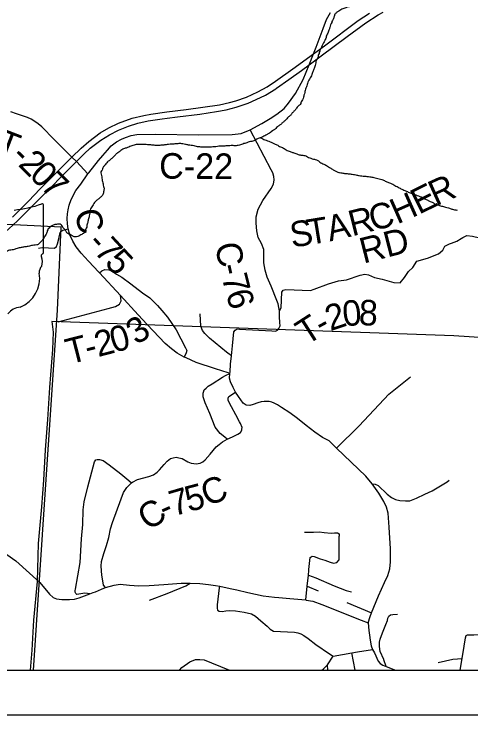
# Model space of a CAD drawing. Extents: x -20.2 to 34, y 0 to 22.
# Drawn here: x 3.418 to 4.435, y 14 to 15.559 of the extents above; entities that cross this region are included whole.
import ezdxf

# ---------------------------------------------------------------- set-up
doc = ezdxf.new("R2010")
doc.units = 0
for name, color, linetype in [('Default', 7, 'Continuous'), ('GM_X_City_Street', 7, 'Continuous'), ('GM_X_County_Road', 7, 'Continuous'), ('GM_X_County_Road_Text', 7, 'Continuous'), ('GM_X_Minor_River', 7, 'Continuous'), ('GM_X_State_Route', 7, 'Continuous'), ('GM_X_State_Shield', 7, 'Continuous'), ('GM_X_Township_Road', 7, 'Continuous'), ('GM_X_Township_Road_Text', 7, 'Continuous'), ('SH_Cut_Line', 7, 'Continuous'), ('SH_Data', 7, 'Continuous')]:
    doc.layers.add(name, color=color, linetype=linetype)

msp = doc.modelspace()

# ---------------------------------------------------------------- linework, layer by layer
at = {"layer": 'Default'}
for points in [[(4.5, 19.1063), (4.129, 19.1285), (4.084, 19.1299), (2.9253, 19.1951), (2.1, 19.2514), (2.1, 14.1), (5.3953, 14.1)], [(4.4653, 14.8388), (4.3965, 14.843), (3.5022, 14.8753), (3.505, 14.8511), (3.5035, 14.8128), (3.4972, 14.7282), (3.4927, 14.6569), (3.487, 14.5895), (3.4833, 14.522), (3.4792, 14.4632), (3.4719, 14.3817), (3.4691, 14.2968), (3.461, 14.2107), (3.4573, 14.144), (3.454, 14.1), (5.4224, 14.1)]]:
    msp.add_lwpolyline(points, dxfattribs=at)
msp.add_lwpolyline([(3.3273, 14.1), (3.4615, 14.1), (3.4877, 14.5012), (3.5149, 14.9006), (3.5228, 15.0852), (2.4641, 15.1369), (2.4117, 14.1451)], close=True, dxfattribs=at)
at = {"layer": 'GM_X_City_Street'}
for p, q in [((4.0705, 14.2863), (4.095, 14.2764)), ((4.1583, 14.2505), (4.2138, 14.2271)), ((4.1771, 14.1), (4.17, 14.1383)), ((4.116, 14.1), (4.1153, 14.1119))]:
    msp.add_line(p, q, dxfattribs=at)
for points in [[(3.6082, 14.9837), (3.6134, 14.9879), (3.6203, 14.9908), (3.6287, 14.9904), (3.6352, 14.9877), (3.6461, 14.9801), (3.6581, 14.9734), (3.6776, 14.9593), (3.704, 14.9392), (3.72, 14.9275), (3.737, 14.9111), (3.747, 14.8998), (3.7594, 14.8851), (3.7695, 14.8704), (3.7791, 14.8565), (3.7999, 14.8169), (3.8022, 14.8104), (3.8014, 14.8054), (3.7968, 14.7961)], [(3.9016, 14.7987), (3.8908, 14.8073), (3.8527, 14.8384), (3.8423, 14.8488), (3.8371, 14.8553), (3.834, 14.8646), (3.8319, 14.8921)], [(3.8984, 14.7595), (3.8987, 14.7631), (3.8998, 14.78), (3.9016, 14.7987), (3.9039, 14.8211), (3.907, 14.8522), (3.9099, 14.856), (3.9147, 14.8585), (3.9201, 14.858), (3.9918, 14.8542), (3.9997, 14.8537), (4.0042, 14.8558), (4.0076, 14.8596), (4.01, 14.8657)], [(4.1356, 14.5931), (4.186, 14.6429), (4.2524, 14.7135), (4.3005, 14.7522)], [(3.5869, 14.2692), (3.5816, 14.2704), (3.5754, 14.2708), (3.5578, 14.2683), (3.5552, 14.2704), (3.554, 14.2728), (3.5539, 14.277), (3.5549, 14.2802), (3.5652, 14.3393), (3.5684, 14.3918), (3.5709, 14.4234), (3.5721, 14.4566), (3.5739, 14.4743), (3.5823, 14.5071), (3.5969, 14.5633), (3.6001, 14.5678), (3.603, 14.5684), (3.6078, 14.5682), (3.616, 14.5659), (3.6298, 14.5566), (3.6558, 14.5362), (3.6738, 14.5218), (3.6794, 14.5161)], [(4.2153, 14.5138), (4.222, 14.5136), (4.2281, 14.5102), (4.2486, 14.4909), (4.258, 14.4838), (4.2673, 14.4796), (4.2767, 14.4773), (4.2889, 14.4764), (4.299, 14.476), (4.3135, 14.4819), (4.3319, 14.4909), (4.3487, 14.4989), (4.3818, 14.5188), (4.3867, 14.5219)], [(4.0644, 14.4064), (4.0848, 14.4068), (4.0974, 14.4072), (4.1083, 14.4057), (4.1236, 14.4043), (4.1312, 14.4054), (4.1381, 14.4049), (4.1418, 14.4028), (4.1416, 14.398)], [(4.0772, 14.3499), (4.0814, 14.3533), (4.0857, 14.3523), (4.0995, 14.3474), (4.11, 14.3443), (4.1217, 14.3396), (4.1293, 14.3375), (4.1364, 14.3388), (4.1418, 14.3454), (4.1416, 14.398)], [(4.0738, 14.3215), (4.0739, 14.3233), (4.0772, 14.3499)], [(4.0673, 14.2558), (4.0705, 14.2863), (4.073, 14.3107), (4.0738, 14.3215)], [(4.073, 14.3107), (4.0898, 14.3052), (4.1307, 14.2874), (4.1572, 14.2765), (4.1687, 14.2742)], [(3.7197, 14.2554), (3.7589, 14.2701), (3.8006, 14.2874), (3.8096, 14.2933)], [(3.8759, 14.2865), (3.8743, 14.2827), (3.8703, 14.2453), (3.8703, 14.2374), (3.8707, 14.2329), (3.8745, 14.2306), (3.8815, 14.2302), (3.889, 14.232), (3.8973, 14.2327), (3.9106, 14.2318), (3.9302, 14.2286), (3.9465, 14.2248), (3.9557, 14.22), (3.9672, 14.2094), (3.9812, 14.1977), (3.9879, 14.1912), (3.9958, 14.1862), (4.0109, 14.1858), (4.0263, 14.1853), (4.0425, 14.1842), (4.0499, 14.1828), (4.0562, 14.1806), (4.063, 14.177), (4.0727, 14.17), (4.0894, 14.1571), (4.1198, 14.1362), (4.1284, 14.131)], [(4.411, 14.1), (4.4154, 14.1253), (4.4198, 14.1531), (4.4225, 14.1718), (4.4242, 14.1766), (4.4272, 14.1781), (4.4311, 14.1781), (4.4414, 14.1783), (4.453, 14.1789), (4.4897, 14.1813), (4.4976, 14.1829), (4.5025, 14.1854), (4.5062, 14.1915), (4.5092, 14.2008), (4.5142, 14.2102), (4.5199, 14.2163), (4.5461, 14.2289), (4.5662, 14.2392)], [(4.2407, 14.1231), (4.2331, 14.1409), (4.2312, 14.1521), (4.2312, 14.162), (4.2327, 14.1687), (4.2382, 14.1827), (4.2457, 14.2016), (4.249, 14.2102), (4.2501, 14.2152), (4.2522, 14.2199), (4.2558, 14.2228), (4.261, 14.2236), (4.2713, 14.2245)], [(4.1284, 14.131), (4.17, 14.1383), (4.1822, 14.1401), (4.2156, 14.1454)], [(4.1033, 14.1), (4.1065, 14.1023), (4.1153, 14.1119), (4.1284, 14.131)], [(4.3619, 14.1168), (4.3942, 14.124), (4.4154, 14.1253)], [(3.7863, 14.1), (3.7914, 14.1053), (3.8091, 14.1183), (3.8217, 14.1235), (3.8317, 14.1237), (3.8413, 14.1225), (3.8941, 14.1013), (3.898, 14.1)], [(4.2461, 14.108), (4.2411, 14.1223), (4.2407, 14.1231)]]:
    msp.add_lwpolyline(points, dxfattribs=at)
at = {"layer": 'GM_X_County_Road'}
for p, q in [((3.8961, 14.7086), (3.9111, 14.7178)), ((3.9196, 14.6521), (3.9113, 14.6679))]:
    msp.add_line(p, q, dxfattribs=at)
for points in [[(3.6156, 15.2444), (3.6256, 15.2566), (3.6342, 15.2662), (3.6461, 15.2748), (3.6568, 15.2807), (3.6662, 15.2847), (3.6784, 15.2885), (3.6916, 15.291), (3.7332, 15.2916), (3.8274, 15.2907), (3.9037, 15.2908), (3.9232, 15.2931), (3.9435, 15.3017), (3.9697, 15.3154), (3.9879, 15.3265), (4.003, 15.3361), (4.0188, 15.3486), (4.0287, 15.361), (4.0445, 15.3824), (4.0616, 15.4135), (4.0745, 15.446), (4.0842, 15.4703), (4.0905, 15.485), (4.1061, 15.5269), (4.1137, 15.547), (4.1223, 15.5627)], [(4.0085, 14.897), (4.0085, 14.8986), (4.0076, 14.906), (4.006, 14.9148), (4.0026, 14.9216), (3.9906, 14.9534), (3.9812, 14.9739), (3.9767, 14.9895), (3.9742, 15.0059), (3.9737, 15.0354), (3.9688, 15.0487), (3.9613, 15.0623), (3.9582, 15.0767), (3.9568, 15.0938), (3.9571, 15.108), (3.9613, 15.1249), (3.9719, 15.1443), (3.9904, 15.1709), (3.9958, 15.1809), (3.997, 15.1899), (3.9963, 15.1973), (3.9938, 15.2059), (3.9902, 15.2126), (3.9435, 15.3017)], [(3.5841, 15.2061), (3.6062, 15.2329), (3.6156, 15.2444)], [(3.5557, 15.1662), (3.5664, 15.1809), (3.5822, 15.2038), (3.5841, 15.2061)], [(3.5387, 15.0813), (3.5369, 15.0926), (3.536, 15.1045), (3.5371, 15.115), (3.5383, 15.1232), (3.5406, 15.1339), (3.545, 15.1465), (3.5557, 15.1662)], [(3.5185, 15.0626), (3.5205, 15.0728), (3.5243, 15.0766), (3.5269, 15.0783), (3.5387, 15.0813)], [(3.6082, 14.9837), (3.6067, 14.9852), (3.5834, 15.0097), (3.5677, 15.0269), (3.5561, 15.0414), (3.5488, 15.0535), (3.5419, 15.068), (3.5387, 15.0813)], [(3.4727, 15.038), (3.4802, 15.0401), (3.4947, 15.0391), (3.5081, 15.0386), (3.5127, 15.0418), (3.5146, 15.0481), (3.5184, 15.0619), (3.5185, 15.0626)], [(3.7968, 14.7961), (3.7808, 14.8051), (3.7682, 14.8144), (3.7542, 14.8263), (3.741, 14.84), (3.7145, 14.8685), (3.6944, 14.8903), (3.6549, 14.9329), (3.6082, 14.9837)], [(4.01, 14.8657), (4.0094, 14.8729), (4.0085, 14.8853), (4.0085, 14.897)], [(3.8945, 14.7608), (3.8662, 14.7699), (3.8231, 14.7841), (3.8008, 14.7942), (3.7968, 14.7961)], [(3.8462, 14.7275), (3.8498, 14.7311), (3.8592, 14.7367), (3.8819, 14.7513), (3.8883, 14.7548), (3.8984, 14.7595)], [(3.9807, 14.6975), (3.9746, 14.6975), (3.9683, 14.6964), (3.9604, 14.6941), (3.9505, 14.6903), (3.9424, 14.6887), (3.9347, 14.6889), (3.9282, 14.6932), (3.9178, 14.7082), (3.9111, 14.7178), (3.9059, 14.7282), (3.9, 14.741), (3.8975, 14.7489), (3.8984, 14.7595), (3.8945, 14.7608)], [(3.8924, 14.6133), (3.8874, 14.6182), (3.8767, 14.6262), (3.8655, 14.6398), (3.8536, 14.6709), (3.843, 14.6944), (3.8387, 14.7074), (3.8387, 14.7155), (3.8396, 14.7183), (3.8414, 14.7232), (3.8455, 14.7268), (3.8462, 14.7275)], [(3.9113, 14.6679), (3.9023, 14.6853), (3.8946, 14.6991), (3.8946, 14.7047), (3.8961, 14.7086)], [(4.2058, 14.2047), (4.2106, 14.2191), (4.2138, 14.2271), (4.2289, 14.2652), (4.2423, 14.2943), (4.2499, 14.3101), (4.2541, 14.3252), (4.2562, 14.3404), (4.256, 14.3696), (4.253, 14.4175), (4.2507, 14.4491), (4.2467, 14.4624), (4.2413, 14.4747), (4.2302, 14.4932), (4.2153, 14.5138), (4.201, 14.5308), (4.1356, 14.5931), (4.119, 14.6094), (4.1045, 14.6174), (4.0871, 14.6291), (4.0684, 14.6436), (4.0486, 14.6592), (4.0315, 14.6718), (4.0132, 14.684), (4.0044, 14.6896), (3.9972, 14.6935), (3.9915, 14.6955), (3.9857, 14.6971), (3.9807, 14.6975)], [(3.9249, 14.6355), (3.9255, 14.6391), (3.9217, 14.6481), (3.9196, 14.6521)], [(3.8973, 14.6157), (3.9054, 14.6195), (3.916, 14.6245), (3.9221, 14.6283), (3.9246, 14.6337), (3.9249, 14.6355)], [(3.6214, 14.2838), (3.6171, 14.2886), (3.616, 14.2938), (3.6137, 14.3113), (3.6121, 14.3309), (3.6128, 14.3415), (3.618, 14.3594), (3.6241, 14.3767), (3.6286, 14.3945), (3.6326, 14.4141), (3.6372, 14.4281), (3.6565, 14.4809), (3.6615, 14.4948), (3.6687, 14.5059), (3.6746, 14.5122), (3.6794, 14.5161), (3.6818, 14.5181), (3.6928, 14.5237), (3.7176, 14.5302), (3.7282, 14.5343), (3.7364, 14.5397), (3.742, 14.5456), (3.7521, 14.5571), (3.7589, 14.5647), (3.7663, 14.5701), (3.7724, 14.5719), (3.779, 14.5731), (3.7848, 14.5722), (3.7918, 14.5701), (3.8049, 14.5634), (3.8119, 14.5602), (3.818, 14.5591), (3.8236, 14.5586), (3.8322, 14.5604), (3.8384, 14.5633), (3.8437, 14.5674), (3.8543, 14.5801), (3.868, 14.5965), (3.8748, 14.6019), (3.882, 14.6073), (3.8924, 14.6133), (3.8973, 14.6157)], [(3.2968, 14.3829), (3.3253, 14.3816), (3.38, 14.3661), (3.402, 14.3566), (3.4223, 14.3426), (3.4757, 14.2947), (3.4967, 14.2687), (3.5048, 14.2611), (3.5127, 14.2584), (3.5246, 14.2571)], [(3.5246, 14.2571), (3.5256, 14.257), (3.5414, 14.2566), (3.5524, 14.2577), (3.5632, 14.2606), (3.5869, 14.2692), (3.5937, 14.2721), (3.5991, 14.2741), (3.6124, 14.2798), (3.6214, 14.2838), (3.6408, 14.289), (3.6538, 14.2906), (3.6746, 14.2886), (3.6956, 14.2874), (3.7188, 14.2883), (3.751, 14.2904), (3.7902, 14.2929), (3.8096, 14.2933), (3.8315, 14.2922), (3.8509, 14.2899), (3.866, 14.2879), (3.8759, 14.2865), (3.8993, 14.2815)], [(3.8993, 14.2815), (3.914, 14.2784), (3.9383, 14.2726), (3.9728, 14.2651), (3.9976, 14.2624)], [(3.9976, 14.2624), (4.0076, 14.2613), (4.0319, 14.259), (4.0673, 14.2558), (4.0684, 14.2557), (4.0831, 14.2534), (4.1027, 14.246), (4.1904, 14.2108), (4.2058, 14.2047), (4.2077, 14.188), (4.2101, 14.1721)], [(4.2101, 14.1721), (4.2102, 14.1711), (4.2129, 14.154), (4.2156, 14.1454), (4.22, 14.1382), (4.2287, 14.1199), (4.2327, 14.1143), (4.2388, 14.1108), (4.2461, 14.108), (4.2668, 14.1)]]:
    msp.add_lwpolyline(points, dxfattribs=at)
at = {"layer": 'GM_X_Minor_River'}
for points in [[(4.262, 15.6083), (4.2521, 15.6061), (4.2479, 15.6046), (4.2434, 15.6035), (4.2285, 15.599), (4.224, 15.5972), (4.2198, 15.5961), (4.2099, 15.5924), (4.2027, 15.589), (4.1985, 15.5875), (4.1943, 15.5856), (4.1897, 15.5838), (4.1844, 15.5815), (4.1783, 15.5789), (4.1737, 15.5778), (4.168, 15.5767), (4.1635, 15.5753), (4.1593, 15.5741), (4.154, 15.5719), (4.1498, 15.5704), (4.1456, 15.5686), (4.1406, 15.5656), (4.1353, 15.5618), (4.1315, 15.5573), (4.1295, 15.5501), (4.1264, 15.5448), (4.1249, 15.5402), (4.1226, 15.5353), (4.121, 15.5293), (4.1183, 15.5232), (4.1168, 15.5187), (4.1152, 15.5145), (4.1129, 15.5096), (4.1117, 15.5047), (4.1094, 15.4998), (4.1067, 15.4948), (4.1036, 15.4888), (4.1009, 15.4824), (4.0982, 15.4767), (4.0967, 15.4714), (4.0951, 15.4665), (4.0939, 15.4619), (4.0909, 15.457), (4.0893, 15.4502), (4.0885, 15.4449), (4.0869, 15.4403), (4.0854, 15.4362), (4.0823, 15.429), (4.0808, 15.4244), (4.0784, 15.4195), (4.0757, 15.4142), (4.0731, 15.4101), (4.0711, 15.4048), (4.0696, 15.3995), (4.0676, 15.3942), (4.0657, 15.3892), (4.0653, 15.3847), (4.0633, 15.3786), (4.0622, 15.3741), (4.0602, 15.368), (4.0568, 15.3639), (4.056, 15.3597), (4.0502, 15.3541), (4.0468, 15.3499), (4.0422, 15.3439), (4.0372, 15.339), (4.0338, 15.3341), (4.0288, 15.3303), (4.025, 15.3262), (4.0208, 15.3216), (4.0154, 15.3171), (4.0105, 15.3126), (4.0044, 15.3085), (4.0005, 15.3043), (3.9952, 15.3006), (3.9906, 15.2972), (3.9864, 15.2942), (3.9811, 15.2912), (3.9761, 15.2882), (3.9678, 15.2845), (3.9636, 15.283), (3.9586, 15.2807), (3.9537, 15.2781), (3.9495, 15.2766), (3.9445, 15.2752), (3.9388, 15.2737), (3.9339, 15.2718), (3.9297, 15.2707), (3.9194, 15.2674), (3.9103, 15.2659), (3.9058, 15.2663), (3.9012, 15.2664), (3.8959, 15.266), (3.8917, 15.2657), (3.8872, 15.2654), (3.883, 15.265), (3.8784, 15.2654)], [(3.9664, 15.284), (3.9764, 15.2791), (3.9821, 15.2771), (3.9878, 15.2748), (3.992, 15.2736), (3.9976, 15.2702), (4.0048, 15.2671), (4.009, 15.2644), (4.0131, 15.2629), (4.0214, 15.2582), (4.0256, 15.2555), (4.0301, 15.254), (4.0343, 15.2524), (4.0407, 15.2505), (4.0453, 15.2489), (4.0525, 15.2462), (4.0566, 15.2454), (4.0608, 15.245), (4.0691, 15.2427), (4.0737, 15.24), (4.0786, 15.2381), (4.0843, 15.2365), (4.0884, 15.2353), (4.0941, 15.2334), (4.1005, 15.2284), (4.1054, 15.2261), (4.1137, 15.2218), (4.1179, 15.2191), (4.1228, 15.2161), (4.13, 15.2118), (4.1353, 15.2091), (4.1425, 15.2064), (4.1478, 15.2056), (4.1519, 15.2048), (4.1595, 15.204), (4.1682, 15.2032), (4.1732, 15.2024), (4.1789, 15.2012), (4.1861, 15.1996), (4.1917, 15.1988), (4.1989, 15.1984), (4.2035, 15.198), (4.2099, 15.1972), (4.2187, 15.1956), (4.2308, 15.1925), (4.2368, 15.1913), (4.244, 15.1874), (4.2516, 15.1843), (4.2607, 15.1805), (4.2705, 15.1751), (4.2792, 15.1704), (4.2875, 15.1666), (4.2954, 15.1631), (4.3041, 15.1596), (4.3091, 15.1577), (4.3155, 15.1554), (4.3208, 15.1534), (4.3276, 15.1507), (4.3325, 15.148), (4.3386, 15.1453), (4.3438, 15.1422), (4.3488, 15.1403), (4.3541, 15.1372), (4.3586, 15.1353), (4.3647, 15.1333), (4.3692, 15.1318), (4.3741, 15.131), (4.3783, 15.1294), (4.3847, 15.1279), (4.3889, 15.1263), (4.3957, 15.1244), (4.401, 15.1232), (4.4052, 15.1232)], [(3.8784, 15.2654), (3.8739, 15.2651), (3.8674, 15.2636), (3.8602, 15.2633), (3.8545, 15.2629), (3.8378, 15.2631), (3.8291, 15.2635), (3.8242, 15.2643), (3.8185, 15.2659), (3.8064, 15.2675), (3.7995, 15.2691), (3.7939, 15.2702), (3.7893, 15.2707), (3.7848, 15.2707), (3.7798, 15.2704), (3.7715, 15.2697), (3.7654, 15.2693), (3.7586, 15.2686), (3.7513, 15.2675), (3.7422, 15.2669), (3.7373, 15.2665), (3.732, 15.2669), (3.7221, 15.2678), (3.7176, 15.2682), (3.7119, 15.2686), (3.7073, 15.269), (3.7024, 15.2691), (3.6971, 15.2687), (3.6918, 15.2688), (3.6876, 15.268), (3.6823, 15.2666), (3.6777, 15.2655), (3.6732, 15.2632), (3.6674, 15.261), (3.6602, 15.2584), (3.656, 15.2554), (3.6491, 15.2505), (3.6442, 15.2467), (3.6388, 15.2407), (3.6327, 15.2354), (3.6262, 15.2302), (3.6224, 15.226), (3.6193, 15.2219), (3.6155, 15.217), (3.614, 15.212), (3.6109, 15.2079), (3.6116, 15.2029), (3.6131, 15.1969), (3.6138, 15.1912), (3.616, 15.1813), (3.6167, 15.1756), (3.6182, 15.1714), (3.6174, 15.1638), (3.6166, 15.1593), (3.6143, 15.1551), (3.6093, 15.1506), (3.6036, 15.1457), (3.5986, 15.1416), (3.5956, 15.1374), (3.5929, 15.1325), (3.5898, 15.1279), (3.5871, 15.1227), (3.5867, 15.1162), (3.5855, 15.1105), (3.5847, 15.106), (3.5831, 15.1014), (3.5816, 15.0938), (3.58, 15.0893), (3.5796, 15.0851), (3.5777, 15.081), (3.575, 15.0734), (3.5689, 15.0689), (3.5643, 15.0663), (3.5597, 15.0644), (3.5536, 15.0633), (3.5476, 15.0656), (3.5427, 15.0687), (3.5378, 15.0706), (3.534, 15.0752), (3.5302, 15.0802), (3.5269, 15.0844), (3.5246, 15.0886), (3.5205, 15.0913), (3.5148, 15.0913), (3.5106, 15.091), (3.5037, 15.0888), (3.4976, 15.085), (3.4942, 15.0809), (3.4919, 15.0767), (3.4896, 15.0691), (3.4865, 15.065), (3.4834, 15.0593), (3.4796, 15.0544), (3.4738, 15.0484), (3.4685, 15.0454), (3.4617, 15.0447), (3.4571, 15.0439)], [(3.4571, 15.0439), (3.4526, 15.0428), (3.4469, 15.0417), (3.4393, 15.0407), (3.4317, 15.0392), (3.4275, 15.0385), (3.4222, 15.0366), (3.4138, 15.0344), (3.4081, 15.0337), (3.4035, 15.0318), (3.3993, 15.0296), (3.394, 15.027), (3.3883, 15.024), (3.3841, 15.0229), (3.3752, 15.0207)]]:
    msp.add_spline(points, degree=3, dxfattribs=at)
at = {"layer": 'GM_X_State_Route'}
for points in [[(3.4144, 15.1073), (3.4504, 15.1428), (3.4764, 15.1701), (3.5466, 15.2407), (3.567, 15.2608), (3.5844, 15.2758), (3.61, 15.2947), (3.6291, 15.3059), (3.6501, 15.3163), (3.6811, 15.3272), (3.7071, 15.3332), (3.7226, 15.3365), (3.7577, 15.3413), (3.801, 15.3464), (3.8754, 15.357), (3.8978, 15.362), (3.9117, 15.3658), (3.9352, 15.374), (3.9606, 15.3857), (3.9811, 15.397), (4.0001, 15.4096), (4.0388, 15.4371), (4.0842, 15.4703), (4.1092, 15.4886), (4.184, 15.5446), (4.209, 15.5612)], [(3.5567, 15.2308), (3.5738, 15.248), (3.5873, 15.2604), (3.611, 15.2786), (3.6303, 15.2906), (3.6502, 15.3009), (3.6727, 15.3099), (3.6933, 15.3166), (3.7162, 15.3212), (3.7475, 15.3261), (3.7588, 15.3275), (3.782, 15.3303), (3.8318, 15.3365), (3.8686, 15.342), (3.8904, 15.3462), (3.9122, 15.352), (3.928, 15.3572), (3.9394, 15.361), (3.9571, 15.3686), (3.9775, 15.3787), (4.0003, 15.3928), (4.0024, 15.3942), (4.0299, 15.4131), (4.0577, 15.4335), (4.0745, 15.446), (4.1014, 15.466), (4.1595, 15.5092), (4.2013, 15.5392), (4.2287, 15.5571), (4.2395, 15.563)], [(3.3101, 15.0079), (3.3197, 15.0118), (3.3858, 15.0637), (3.4061, 15.0813), (3.4253, 15.0993), (3.467, 15.1407), (3.5567, 15.2308)]]:
    msp.add_lwpolyline(points, dxfattribs=at)
at = {"layer": 'GM_X_State_Shield'}
for p, q in [((3.4833, 15.0287), (3.4833, 15.1334)), ((3.4833, 15.0288), (3.4833, 15.0287))]:
    msp.add_line(p, q, dxfattribs=at)
for centre, radius, start, end in [((3.3894, 15.4013), 0.2796, 275.8445, 288.9065), ((3.4804, 15.1339), 0.00294, 351.8621, 97.738), ((3.4827, 15.0211), 0.00454, 107.944, 210.337), ((3.4538, 15.0078), 0.0273, 340.033, 23.6496), ((3.4802, 15.0283), 0.00314, 289.6038, 7.7341), ((3.4939, 14.9849), 0.0198, 136.8065, 186.9296), ((3.4051, 14.9716), 0.0699, 292.3089, 8.9858), ((3.4346, 14.8687), 0.0383, 94.4031, 142.5768)]:
    msp.add_arc(centre, radius, start, end, dxfattribs=at)
at = {"layer": 'GM_X_Township_Road'}
for p, q in [((3.5466, 15.2407), (3.5396, 15.2476)), ((3.5162, 14.8743), (3.6271, 14.9038))]:
    msp.add_line(p, q, dxfattribs=at)
for points in [[(3.5396, 15.2476), (3.5071, 15.2799), (3.4799, 15.3078), (3.4714, 15.315), (3.4646, 15.32), (3.4564, 15.325), (3.4477, 15.3289), (3.4233, 15.337), (3.4111, 15.3418)], [(3.5822, 15.2038), (3.5567, 15.2308), (3.5466, 15.2407)], [(4.4133, 15.0595), (4.417, 15.0617), (4.426, 15.0664), (4.4381, 15.0653), (4.4541, 15.0611), (4.4681, 15.0615), (4.4818, 15.0599), (4.4971, 15.0575), (4.5047, 15.055), (4.5209, 15.0642), (4.5466, 15.0819)], [(4.0085, 14.8986), (4.0123, 14.9059), (4.0143, 14.9407), (4.0169, 14.9445), (4.0232, 14.9463), (4.0776, 14.9443), (4.0861, 14.9472), (4.118, 14.9589), (4.1401, 14.9657), (4.1579, 14.9682), (4.1885, 14.9785), (4.1984, 14.9801), (4.2067, 14.979), (4.22, 14.9731), (4.2373, 14.9691), (4.2634, 14.9621), (4.2771, 14.9614), (4.2867, 14.9727), (4.2957, 14.9864), (4.3057, 14.9952), (4.3146, 15.0091), (4.3382, 15.0158), (4.3623, 15.0255), (4.3722, 15.0338), (4.3765, 15.0426), (4.3875, 15.0476)], [(4.3875, 15.0476), (4.3916, 15.0494), (4.4035, 15.0536), (4.4133, 15.0595)], [(3.6271, 14.9038), (3.6438, 14.9082), (3.6528, 14.9135), (3.6564, 14.9209), (3.6549, 14.9329)]]:
    msp.add_lwpolyline(points, dxfattribs=at)
at = {"layer": 'SH_Cut_Line'}
msp.add_lwpolyline([(5.7735, 14.1), (8.9, 14.1), (8.9, 20.9), (2.1, 20.9), (2.1, 14.1), (5.3953, 14.1), (5.7268, 14.1076)], close=True, dxfattribs=at)
at = {"layer": 'SH_Data'}
for p, q in [((2.1, 14.1), (8.9, 14.1)), ((2, 14), (9, 14))]:
    msp.add_line(p, q, dxfattribs=at)

# ---------------------------------------------------------------- texts
at = {"layer": 'GM_X_County_Road_Text'}
for s, height, rotation, p in [('C-22', 0.05682, 359.6557, (3.7408, 15.193)), ('C', 0.0568, 284.3614, (3.5518, 15.1187)), ('-', 0.0568, 312.9328, (3.578, 15.047)), ('7', 0.0568, 312.8315, (3.5937, 15.0301)), ('C', 0.0568, 281.3574, (3.8648, 15.0459)), ('5', 0.0568, 312.9668, (3.6174, 15.0045)), ('-', 0.0568, 282.5396, (3.8743, 14.9989)), ('7', 0.0568, 284.1156, (3.8798, 14.9745)), ('6', 0.0568, 285.976, (3.8888, 14.9386)), ('C', 0.0568, 22.6836, (3.8484, 14.4629)), ('5', 0.0568, 14.685, (3.8063, 14.4512)), ('7', 0.0568, 16.3, (3.7731, 14.4415)), ('C', 0.0568, 33.0406, (3.7167, 14.4084)), ('-', 0.0568, 23.9807, (3.7537, 14.4327))]:
    msp.add_text(s, height=height, rotation=rotation, dxfattribs=at).set_placement(p)
at = {"layer": 'GM_X_Township_Road_Text'}
for s, height, rotation, p in [('T', 0.0568, 338.9554, (3.3739, 15.2513)), ('-', 0.0568, 315.574, (3.4084, 15.2393)), ('2', 0.0568, 315.0368, (3.425, 15.2231)), ('0', 0.0568, 315, (3.4497, 15.1984)), ('7', 0.0568, 315.0045, (3.4745, 15.1736)), ('R', 0.0568, 24.339, (4.3566, 15.1309)), ('E', 0.0568, 26.435, (4.3191, 15.1122)), ('H', 0.0568, 23.9556, (4.2709, 15.0908)), ('C', 0.0568, 14.1233, (4.2156, 15.0759)), ('R', 0.0568, 14.1274, (4.1704, 15.0645)), ('T', 0.0568, 9.2108, (4.0745, 15.0453)), ('A', 0.0568, 13.0808, (4.1206, 15.0529)), ('S', 0.0568, 9.2147, (4.0367, 15.0392)), ('RD', 0.05682, 14.3933, (4.1955, 15.0037)), ('0', 0.0568, 6.0477, (4.1518, 14.8637)), ('8', 0.0568, 357.616, (4.1844, 14.8673)), ('2', 0.0568, 18.6127, (4.1218, 14.8533)), ('T', 0.0568, 32.6559, (4.0688, 14.8208)), ('3', 0.0568, 32.64, (3.6905, 14.8219)), ('-', 0.0568, 28.4609, (4.1037, 14.8432)), ('2', 0.0568, 14.498, (3.605, 14.7959)), ('0', 0.0568, 15.5836, (3.6401, 14.805)), ('T', 0.0568, 14.3429, (3.5411, 14.7796)), ('-', 0.0568, 14.3771, (3.5823, 14.7901))]:
    msp.add_text(s, height=height, rotation=rotation, dxfattribs=at).set_placement(p)

doc.saveas('drawing.dxf')
